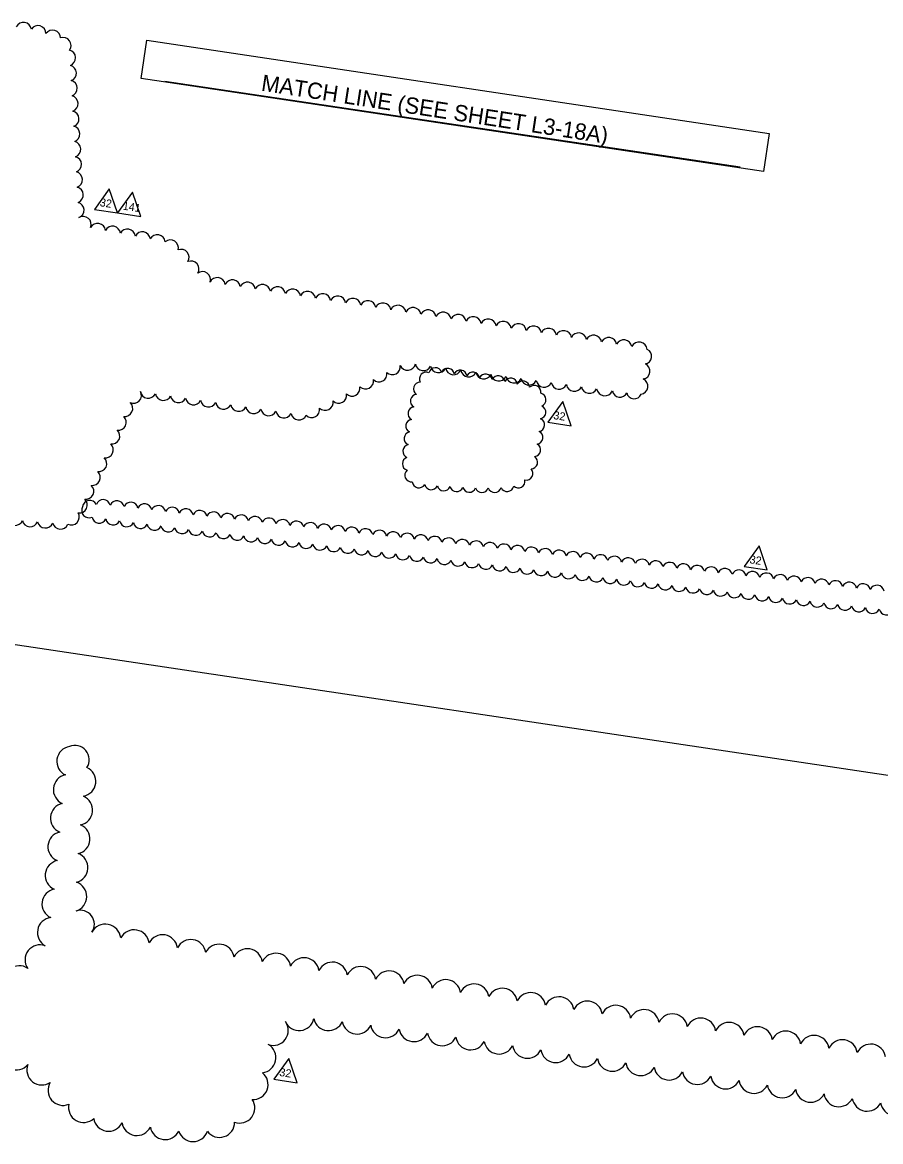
# Model space of a CAD drawing. Extents: x 924436 to 925782, y 636346 to 637319.
# Drawn here: x 924943 to 925365, y 636734 to 637284 of the extents above; entities that cross this region are included whole.
import ezdxf

# ---------------------------------------------------------------- set-up
doc = ezdxf.new("R2010")
doc.units = 0
for name, color, linetype in [('ActivePointCell_dp', 7, 'Continuous'), ('AdhocPoint_dp', 7, 'Continuous'), ('Cloud_dp', 7, 'Continuous'), ('MatchLines_dp', 7, 'Continuous')]:
    doc.layers.add(name, color=color, linetype=linetype)

msp = doc.modelspace()

# ---------------------------------------------------------------- linework, layer by layer
at = {"layer": 'ActivePointCell_dp'}
msp.add_line((924609.88, 637027.58), (925702.36, 636864), dxfattribs=at)
at = {"layer": 'AdhocPoint_dp'}
msp.add_lwpolyline([(925003.9, 637275.4), (925310.19, 637229.54), (925307.39, 637210.8), (925001.09, 637256.67)], close=True, dxfattribs=at)
at = {"layer": 'Cloud_dp'}
for points in [[(924985.41, 637202.37), (924978.05, 637192.22), (924989.47, 637190.51)], [(924996.83, 637200.65), (924989.47, 637190.51), (925000.9, 637188.8)], [(925208.65, 637097.67), (925201.29, 637087.52), (925212.72, 637085.81)], [(925305.22, 637026.73), (925297.86, 637016.58), (925309.29, 637014.87)], [(925073.78, 636774.55), (925066.42, 636764.4), (925077.84, 636762.69)]]:
    msp.add_lwpolyline(points, close=True, dxfattribs=at)
for centre, radius, start, end in [((924943.16, 637280.28), 3.94, 9.273, 154.273), ((924950.28, 637278.7), 3.92, 0.6236, 145.6236), ((924957.45, 637276.52), 3.93, 0.6236, 145.6236), ((924962.65, 637272.86), 3.92, 324.0345, 109.0345), ((924964.85, 637266.74), 3.94, 290.7292, 75.7292), ((924965.28, 637259.24), 3.93, 290.7292, 75.7292), ((924965.7, 637251.76), 3.93, 290.7292, 75.7292), ((924966.12, 637244.27), 3.93, 290.7292, 75.7292), ((924966.55, 637236.79), 3.93, 290.7292, 75.7292), ((924966.97, 637229.31), 3.93, 290.7292, 75.7292), ((924967.39, 637221.82), 3.93, 290.7292, 75.7292), ((924967.81, 637214.34), 3.93, 290.7292, 75.7292), ((924968.24, 637206.85), 3.93, 290.7292, 75.7292), ((924968.66, 637199.37), 3.93, 290.7292, 75.7292), ((924969.08, 637191.88), 3.93, 290.7292, 75.7292), ((924972.53, 637184.86), 3.92, 336.5968, 121.5968), ((924979.59, 637181.45), 3.93, 6.7591, 151.7591), ((924986.96, 637180.05), 3.93, 6.7591, 151.7591), ((924994.32, 637178.65), 3.93, 6.7591, 151.7591), ((925001.69, 637177.26), 3.93, 6.7591, 151.7591), ((925009.05, 637175.86), 3.93, 6.7591, 151.7591), ((925015.48, 637173.3), 3.93, 344.9092, 129.9092), ((925020.77, 637168.65), 3.93, 327.4688, 112.4688), ((925025.59, 637162.91), 3.93, 327.4688, 112.4688), ((925031.3, 637157.68), 3.93, 342.5622, 127.5622), ((925038.57, 637154.77), 3.93, 8.8026, 153.8026), ((925045.98, 637153.64), 3.93, 8.8026, 153.8026), ((925053.39, 637152.5), 3.93, 8.8026, 153.8026), ((925060.8, 637151.37), 3.93, 8.8026, 153.8026), ((925068.21, 637150.24), 3.93, 8.8026, 153.8026), ((925075.62, 637149.1), 3.93, 8.8026, 153.8026), ((925083.03, 637147.97), 3.93, 8.8026, 153.8026), ((925090.44, 637146.83), 3.93, 8.8026, 153.8026), ((925097.85, 637145.7), 3.93, 8.8026, 153.8026), ((925105.26, 637144.57), 3.93, 8.8026, 153.8026), ((925112.67, 637143.43), 3.93, 8.8026, 153.8026), ((925120.08, 637142.3), 3.93, 8.8026, 153.8026), ((925127.49, 637141.17), 3.93, 8.8026, 153.8026), ((925134.9, 637140.03), 3.93, 8.8026, 153.8026), ((925142.31, 637138.9), 3.93, 8.8026, 153.8026), ((925149.72, 637137.77), 3.93, 8.8026, 153.8026), ((925157.13, 637136.63), 3.93, 8.8026, 153.8026), ((925164.54, 637135.5), 3.93, 8.8026, 153.8026), ((925171.95, 637134.37), 3.93, 8.8026, 153.8026), ((925179.36, 637133.23), 3.93, 8.8026, 153.8026), ((925186.77, 637132.1), 3.93, 8.8026, 153.8026), ((925194.18, 637130.96), 3.93, 8.8026, 153.8026), ((925201.59, 637129.83), 3.93, 8.8026, 153.8026), ((925209, 637128.7), 3.93, 8.8026, 153.8026), ((925216.41, 637127.56), 3.93, 8.8026, 153.8026), ((925223.82, 637126.43), 3.93, 8.8026, 153.8026), ((925231.23, 637125.3), 3.93, 8.8026, 153.8026), ((925238.64, 637124.16), 3.93, 8.8026, 153.8026), ((925246.16, 637122.86), 4.1, 7.3053, 152.3053), ((925248.61, 637119.96), 3.78, 279.7145, 64.7145), ((925124.74, 637114.82), 3.89, 225.4195, 10.4195), ((925132.24, 637117.05), 3.97, 202.5288, 347.5288), ((925139.99, 637116.85), 3.93, 189.7145, 334.7145), ((925145.95, 637111.05), 3.29, 21.0614, 166.0614), ((925147.42, 637115.83), 3.93, 189.7145, 334.7145), ((925151.97, 637110.78), 3.29, 8.9841, 153.9841), ((925154.84, 637114.82), 3.93, 189.7145, 334.7145), ((925158.18, 637109.86), 3.29, 8.9841, 153.9841), ((925162.27, 637113.8), 3.93, 189.7145, 334.7145), ((925247.57, 637112.68), 3.93, 279.7145, 64.7145), ((925111.52, 637107.83), 3.93, 225.4195, 10.4195), ((925118.14, 637111.34), 3.93, 225.4195, 10.4195), ((925138.48, 637103.96), 3.29, 90.2698, 235.2698), ((925141.33, 637108.87), 3.29, 64.4114, 209.4114), ((925164.39, 637108.93), 3.29, 8.9841, 153.9841), ((925169.7, 637112.79), 3.93, 189.7145, 334.7145), ((925170.6, 637108), 3.29, 8.9841, 153.9841), ((925177.13, 637111.77), 3.93, 189.7145, 334.7145), ((925176.79, 637107.04), 3.29, 8.44, 153.44), ((925182.94, 637105.95), 3.29, 6.4984, 151.4984), ((925184.55, 637110.76), 3.93, 189.7145, 334.7145), ((925188.99, 637104.57), 3.29, 2.7878, 147.7878), ((925191.98, 637109.74), 3.93, 189.7145, 334.7145), ((925199.41, 637108.73), 3.93, 189.7145, 334.7145), ((925206.83, 637107.71), 3.93, 189.7145, 334.7145), ((925246.54, 637105.24), 3.95, 279.7145, 64.7145), ((924997.32, 637100.72), 3.87, 244.8452, 29.8452), ((925004.56, 637103.28), 3.93, 189.2305, 334.2305), ((925011.97, 637102.2), 3.93, 189.2305, 334.2305), ((925098.27, 637100.81), 3.93, 225.4195, 10.4195), ((925104.89, 637104.32), 3.93, 225.4195, 10.4195), ((925194.58, 637102.38), 3.29, 349.4042, 134.4042), ((925197.06, 637098.57), 3.29, 291.723, 76.723), ((925214.26, 637106.7), 3.93, 189.7145, 334.7145), ((925221.69, 637105.68), 3.93, 189.7145, 334.7145), ((925229.33, 637104.7), 4.15, 189.7145, 334.7145), ((925236.74, 637103.56), 3.71, 189.7145, 334.7145), ((925243.75, 637102.78), 3.74, 192.4578, 337.4578), ((924993, 637094.32), 3.94, 262.2944, 47.2944), ((925019.39, 637101.13), 3.93, 189.2305, 334.2305), ((925026.81, 637100.05), 3.93, 189.2305, 334.2305), ((925034.23, 637098.97), 3.93, 189.2305, 334.2305), ((925041.65, 637097.89), 3.93, 189.2305, 334.2305), ((925049.07, 637096.81), 3.93, 189.2305, 334.2305), ((925091.65, 637097.3), 3.93, 225.4195, 10.4195), ((925136.9, 637097.98), 3.29, 95.0863, 240.0863), ((925056.48, 637095.73), 3.93, 189.2305, 334.2305), ((925063.9, 637094.66), 3.93, 189.2305, 334.2305), ((925071.32, 637093.58), 3.93, 189.2305, 334.2305), ((925078.7, 637092.59), 3.91, 190.7053, 335.7053), ((925085.02, 637093.79), 3.93, 225.4195, 10.4195), ((925135.68, 637091.87), 3.29, 97.4125, 242.4125), ((925197.01, 637092.48), 3.29, 282.3479, 67.3479), ((924989.81, 637087.53), 3.93, 262.2944, 47.2944), ((925134.66, 637085.7), 3.29, 98.8718, 243.8718), ((925196.34, 637086.28), 3.29, 280.306, 65.306), ((924986.62, 637080.75), 3.93, 262.2944, 47.2944), ((925133.81, 637079.51), 3.29, 100.4034, 245.4034), ((925195.5, 637080.08), 3.29, 279.1975, 64.1975), ((924983.42, 637073.97), 3.93, 262.2944, 47.2944), ((925133.17, 637073.31), 3.29, 102.8514, 247.8514), ((925194.45, 637073.94), 3.29, 276.4141, 61.4141), ((924980.23, 637067.19), 3.93, 262.2944, 47.2944), ((925132.93, 637067.13), 3.29, 107.7596, 252.7596), ((925192.96, 637067.95), 3.29, 270.6541, 55.6541), ((924977.04, 637060.4), 3.93, 262.2944, 47.2944), ((925134.12, 637061.51), 3.29, 131.1749, 276.1749), ((925190.61, 637062.39), 3.29, 258.5614, 43.5614), ((925137.75, 637058.58), 3.29, 186.0187, 331.0187), ((925186.73, 637058.53), 3.29, 226.1918, 11.1918), ((924973.85, 637053.62), 3.93, 262.2944, 47.2944), ((925143.86, 637057.64), 3.29, 191.4515, 336.4515), ((925150.08, 637057.08), 3.29, 193.2866, 338.2866), ((925156.32, 637056.68), 3.29, 194.3044, 339.3044), ((925162.57, 637056.38), 3.29, 195.3049, 340.3049), ((925168.82, 637056.23), 3.29, 196.8645, 341.8645), ((925175.05, 637056.3), 3.29, 199.353, 344.353), ((925181.22, 637056.76), 3.29, 204.3184, 349.3184), ((924970.65, 637046.84), 3.93, 262.2944, 47.2944), ((924975.84, 637045.49), 3.59, 27.6218, 172.6218), ((924982.38, 637045.88), 3.59, 14.1825, 159.1825), ((924989.15, 637045.33), 3.59, 11.5462, 156.5462), ((924995.95, 637044.6), 3.59, 11.1879, 156.1879), ((925002.73, 637043.81), 3.59, 10.4631, 155.4631), ((925009.51, 637042.95), 3.59, 10.0796, 155.0796), ((924966.68, 637040.96), 3.97, 244.8867, 29.8867), ((924975.39, 637044.17), 3.59, 150.0762, 295.0762), ((925016.33, 637042.13), 3.59, 11.1933, 156.1933), ((925023.13, 637041.38), 3.59, 11.1933, 156.1933), ((925029.93, 637040.62), 3.59, 11.1933, 156.1933), ((925036.74, 637039.87), 3.59, 11.1933, 156.1933), ((925043.54, 637039.12), 3.59, 11.1933, 156.1933), ((925050.34, 637038.37), 3.59, 11.1933, 156.1933), ((925057.14, 637037.62), 3.59, 11.1933, 156.1933), ((924938.97, 637040.69), 3.93, 192.8002, 337.8002), ((924946.44, 637040.08), 3.93, 192.8002, 337.8002), ((924953.91, 637039.46), 3.93, 192.8002, 337.8002), ((924961.37, 637038.85), 3.92, 192.8002, 337.8002), ((924980.45, 637041.51), 3.59, 189.5168, 334.5168), ((924987.22, 637040.59), 3.59, 189.9786, 334.9786), ((924994.01, 637039.71), 3.59, 190.2013, 335.2013), ((925000.79, 637038.85), 3.59, 190.3394, 335.3394), ((925007.58, 637038), 3.59, 190.4359, 335.4359), ((925014.37, 637037.16), 3.59, 190.5082, 335.5082), ((925021.17, 637036.33), 3.59, 190.565, 335.565), ((925063.95, 637036.87), 3.59, 11.1933, 156.1933), ((925070.75, 637036.11), 3.59, 11.1933, 156.1933), ((925077.55, 637035.36), 3.59, 11.1933, 156.1933), ((925084.35, 637034.61), 3.59, 11.1933, 156.1933), ((925091.16, 637033.86), 3.59, 11.1933, 156.1933), ((925097.96, 637033.11), 3.59, 11.1933, 156.1933), ((925104.76, 637032.35), 3.59, 11.1933, 156.1933), ((925027.96, 637035.51), 3.59, 190.6112, 335.6112), ((925034.75, 637034.69), 3.59, 190.6497, 335.6497), ((925041.55, 637033.88), 3.59, 190.6825, 335.6825), ((925048.34, 637033.07), 3.59, 190.7108, 335.7108), ((925055.14, 637032.26), 3.59, 190.7355, 335.7355), ((925061.94, 637031.45), 3.59, 190.7574, 335.7574), ((925068.73, 637030.65), 3.59, 190.777, 335.777), ((925111.57, 637031.6), 3.59, 11.1933, 156.1933), ((925118.37, 637030.85), 3.59, 11.1933, 156.1933), ((925125.17, 637030.1), 3.59, 11.1933, 156.1933), ((925131.97, 637029.35), 3.59, 11.1933, 156.1933), ((925138.78, 637028.6), 3.59, 11.1933, 156.1933), ((925145.58, 637027.84), 3.59, 11.1933, 156.1933), ((925152.38, 637027.09), 3.59, 11.1933, 156.1933), ((925159.18, 637026.34), 3.59, 11.1933, 156.1933), ((925075.53, 637029.85), 3.59, 190.7946, 335.7946), ((925082.33, 637029.05), 3.59, 190.8105, 335.8105), ((925089.12, 637028.26), 3.59, 190.8251, 335.8251), ((925095.92, 637027.46), 3.59, 190.8384, 335.8384), ((925102.72, 637026.67), 3.59, 190.8507, 335.8507), ((925109.52, 637025.88), 3.59, 190.8621, 335.8621), ((925165.99, 637025.59), 3.59, 11.1933, 156.1933), ((925172.79, 637024.84), 3.59, 11.1933, 156.1933), ((925179.59, 637024.08), 3.59, 11.1933, 156.1933), ((925186.39, 637023.33), 3.59, 11.1933, 156.1933), ((925193.2, 637022.58), 3.59, 11.1933, 156.1933), ((925200, 637021.83), 3.59, 11.1933, 156.1933), ((925206.8, 637021.08), 3.59, 11.1933, 156.1933), ((925116.32, 637025.09), 3.59, 190.8727, 335.8727), ((925123.11, 637024.3), 3.59, 190.8825, 335.8825), ((925129.91, 637023.51), 3.59, 190.8917, 335.8917), ((925136.71, 637022.72), 3.59, 190.9004, 335.9004), ((925143.51, 637021.93), 3.59, 190.9085, 335.9085), ((925150.31, 637021.15), 3.59, 190.9161, 335.9161), ((925157.11, 637020.37), 3.59, 190.9233, 335.9233), ((925213.6, 637020.33), 3.59, 11.1933, 156.1933), ((925220.41, 637019.57), 3.59, 11.1933, 156.1933), ((925227.21, 637018.82), 3.59, 11.1933, 156.1933), ((925234.01, 637018.07), 3.59, 11.1933, 156.1933), ((925240.81, 637017.32), 3.59, 11.1933, 156.1933), ((925247.62, 637016.57), 3.59, 11.1933, 156.1933), ((925254.42, 637015.81), 3.59, 11.1933, 156.1933), ((925163.91, 637019.58), 3.59, 190.9302, 335.9302), ((925170.7, 637018.8), 3.59, 190.9366, 335.9366), ((925177.5, 637018.02), 3.59, 190.9428, 335.9428), ((925184.3, 637017.24), 3.59, 190.9487, 335.9487), ((925191.1, 637016.46), 3.59, 190.9542, 335.9542), ((925197.9, 637015.68), 3.59, 190.9596, 335.9596), ((925204.7, 637014.9), 3.59, 190.9647, 335.9647), ((925211.5, 637014.12), 3.59, 190.9695, 335.9695), ((925261.22, 637015.06), 3.59, 11.1933, 156.1933), ((925268.03, 637014.31), 3.59, 11.1933, 156.1933), ((925274.83, 637013.56), 3.59, 11.1933, 156.1933), ((925281.63, 637012.81), 3.59, 11.1933, 156.1933), ((925288.43, 637012.06), 3.59, 11.1933, 156.1933), ((925295.24, 637011.3), 3.59, 11.1933, 156.1933), ((925302.04, 637010.55), 3.59, 11.1933, 156.1933), ((925218.3, 637013.34), 3.59, 190.9742, 335.9742), ((925225.1, 637012.56), 3.59, 190.9787, 335.9787), ((925231.9, 637011.79), 3.59, 190.983, 335.983), ((925238.7, 637011.01), 3.59, 190.9872, 335.9872), ((925245.5, 637010.23), 3.59, 190.9912, 335.9912), ((925252.3, 637009.46), 3.59, 190.995, 335.995), ((925259.1, 637008.68), 3.59, 190.9987, 335.9987), ((925308.84, 637009.8), 3.59, 11.1933, 156.1933), ((925315.64, 637009.05), 3.59, 11.1933, 156.1933), ((925322.45, 637008.3), 3.59, 11.1933, 156.1933), ((925329.25, 637007.54), 3.59, 11.1933, 156.1933), ((925336.05, 637006.79), 3.59, 11.1932, 156.1932), ((925342.85, 637006.04), 3.59, 11.191, 156.191), ((925349.66, 637005.29), 3.59, 11.1881, 156.1881), ((925356.46, 637004.54), 3.59, 11.1851, 156.1851), ((925265.9, 637007.91), 3.59, 191.0023, 336.0023), ((925272.7, 637007.13), 3.59, 191.0057, 336.0057), ((925279.5, 637006.36), 3.59, 191.0091, 336.0091), ((925286.3, 637005.59), 3.59, 191.0123, 336.0123), ((925293.1, 637004.81), 3.59, 191.0154, 336.0154), ((925299.9, 637004.04), 3.59, 191.0185, 336.0185), ((925306.7, 637003.27), 3.59, 191.0214, 336.0214), ((925363.26, 637003.78), 3.59, 11.182, 156.182), ((925313.5, 637002.5), 3.59, 191.0242, 336.0242), ((925320.3, 637001.72), 3.59, 191.0269, 336.0269), ((925327.1, 637000.95), 3.59, 191.0279, 336.0279), ((925333.9, 637000.18), 3.59, 191.0283, 336.0283), ((925340.7, 636999.41), 3.59, 191.0287, 336.0287), ((925347.5, 636998.64), 3.59, 191.0291, 336.0291), ((925354.3, 636997.87), 3.59, 191.0295, 336.0295), ((925361.1, 636997.1), 3.59, 191.03, 336.03), ((925367.9, 636996.32), 3.59, 191.0304, 336.0304), ((924966.98, 636920.73), 7.41, 99.4699, 244.4699), ((924968.45, 636921.51), 7.07, 327.3603, 112.3603), ((924971.3, 636910.92), 7.45, 280.429, 65.429), ((924965.24, 636906.8), 7.4, 101.3663, 246.3663), ((924969.74, 636896.74), 7.44, 282.0121, 67.0121), ((924963.84, 636892.79), 7.4, 102.207, 247.207), ((924968.47, 636882.6), 7.42, 282.699, 67.699), ((924962.57, 636878.74), 7.4, 102.4363, 247.4363), ((924961.23, 636864.67), 7.39, 101.6986, 246.6986), ((924967.44, 636868.45), 7.41, 283.9171, 68.9171), ((924966.9, 636854.23), 7.4, 286.7129, 71.7129), ((924959.63, 636850.61), 7.39, 100.3391, 245.3391), ((924957.41, 636836.54), 7.4, 96.6668, 241.6668), ((924971.23, 636840.7), 6.8, 323.863, 108.863), ((924983.44, 636833.03), 7.65, 6.3926, 151.3926), ((924997.63, 636830.45), 7.43, 7.4518, 152.4518), ((925011.58, 636828.03), 7.41, 7.8732, 152.8732), ((925025.52, 636825.7), 7.4, 8.1204, 153.1204), ((924951.31, 636823.11), 7.38, 69.5515, 214.5515), ((925039.46, 636823.42), 7.4, 8.2882, 153.2882), ((925053.4, 636821.17), 7.4, 8.4117, 153.4117), ((925067.34, 636818.96), 7.4, 8.5075, 153.5075), ((925081.28, 636816.76), 7.4, 8.5847, 153.5847), ((925095.22, 636814.58), 7.4, 8.6486, 153.6486), ((924941.06, 636812.82), 7.39, 55.5961, 200.5961), ((925109.16, 636812.42), 7.4, 8.7026, 153.7026), ((925123.1, 636810.27), 7.4, 8.7491, 153.7491), ((925137.04, 636808.12), 7.4, 8.7896, 153.7896), ((925150.99, 636805.99), 7.39, 8.8254, 153.8254), ((925164.93, 636803.87), 7.39, 8.8573, 153.8573), ((925178.88, 636801.75), 7.39, 8.8859, 153.8859), ((925192.83, 636799.64), 7.39, 8.9118, 153.9118), ((925206.78, 636797.54), 7.39, 8.9353, 153.9353), ((925220.72, 636795.44), 7.39, 8.9569, 153.9569), ((925234.68, 636793.34), 7.41, 8.9765, 153.9765), ((925078.82, 636795.69), 7.38, 203.4594, 348.4594), ((925093.3, 636795.67), 7.39, 191.3679, 336.3679), ((925248.64, 636791.25), 7.39, 8.9686, 153.9686), ((925262.59, 636789.16), 7.39, 8.9418, 153.9418), ((925276.54, 636787.06), 7.39, 8.9128, 153.9128), ((925066.08, 636788.4), 7.4, 251.0597, 36.0597), ((925107.35, 636794.03), 7.4, 190.2747, 335.2747), ((925121.36, 636792.19), 7.4, 189.7887, 334.7887), ((925135.34, 636790.26), 7.39, 189.4963, 334.4963), ((925290.48, 636784.95), 7.39, 8.8812, 153.8812), ((925304.42, 636782.83), 7.39, 8.8466, 153.8466), ((925318.37, 636780.7), 7.39, 8.8086, 153.8086), ((925149.31, 636788.27), 7.39, 189.2953, 334.2953), ((925163.28, 636786.24), 7.39, 189.1463, 334.1463), ((925177.23, 636784.17), 7.39, 189.03, 334.03), ((925332.31, 636778.57), 7.39, 8.7665, 153.7665), ((925346.24, 636776.42), 7.39, 8.7196, 153.7196), ((924939.63, 636776.35), 7.39, 175.0581, 320.0581), ((925060.04, 636774.96), 7.4, 275.5963, 60.5963), ((925191.19, 636782.08), 7.39, 188.936, 333.936), ((925205.13, 636779.97), 7.39, 188.858, 333.858), ((925219.08, 636777.85), 7.39, 188.7918, 333.7918), ((925360.18, 636774.26), 7.39, 8.6669, 153.6669), ((924952.21, 636768.97), 7.4, 159.1404, 304.1404), ((925233.02, 636775.7), 7.39, 188.7349, 333.7349), ((925246.96, 636773.55), 7.39, 188.6851, 333.6851), ((925056.15, 636761.81), 7.39, 266.4398, 51.4398), ((925260.9, 636771.38), 7.39, 188.6411, 333.6411), ((925274.84, 636769.2), 7.39, 188.6019, 333.6019), ((925288.77, 636767.02), 7.39, 188.5667, 333.5667), ((924962.64, 636758.92), 7.4, 147.9697, 292.9697), ((925302.71, 636764.82), 7.39, 188.5348, 333.5348), ((925316.64, 636762.63), 7.4, 188.5317, 333.5317), ((925330.58, 636760.43), 7.39, 188.5597, 333.5597), ((925344.51, 636758.24), 7.39, 188.5908, 333.5908), ((925358.44, 636756.06), 7.39, 188.6255, 333.6255), ((924972.73, 636750.49), 7.39, 167.3422, 312.3422), ((925049.63, 636750.22), 7.39, 249.7551, 34.7551), ((925372.38, 636753.89), 7.39, 188.6647, 333.6647), ((924985.01, 636746.18), 7.39, 188.9841, 333.9841), ((924998.96, 636744.1), 7.39, 188.9841, 333.9841), ((925012.89, 636742.09), 7.4, 189.6099, 334.6099), ((925026.64, 636741.1), 7.4, 197.1656, 342.1656), ((925039.67, 636743.17), 7.4, 215.9007, 0.9007)]:
    msp.add_arc(centre, radius, start, end, dxfattribs=at)
at = {"layer": 'MatchLines_dp'}
msp.add_line((925295.87, 637213.02), (925012.72, 637255.15), dxfattribs=at)

# ---------------------------------------------------------------- texts
at = {"layer": 'Cloud_dp'}
for s, p in [('32', (924980.53, 637193.85)), ('141', (924991.84, 637192.15)), ('32', (925203.78, 637089.15)), ('32', (925300.35, 637018.21)), ('32', (925068.9, 636766.03))]:
    msp.add_text(s, height=3.938, rotation=351.4841, dxfattribs=at).set_placement(p)
at = {"layer": 'MatchLines_dp'}
msp.add_text('MATCH LINE (SEE SHEET L3-18A)', height=8, rotation=351.2644, dxfattribs=at).set_placement((925059.86, 637250.69))

doc.saveas('drawing.dxf')
